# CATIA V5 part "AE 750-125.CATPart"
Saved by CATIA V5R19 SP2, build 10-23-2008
Part number: AE 750-125
Bounding box of the stored display mesh (mm): x -24.865 to 24.865, y -24.997 to 24.997, z 0 to 300
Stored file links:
  C:\Users\Bora\Desktop\3D Katı model\AE serisi\AE 750\AE 750-125.CATPart
  C:\Program Files\Dassault Systemes\B19\intel_a\reffiles\standard\MetricThickPitch.txt
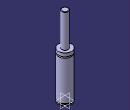
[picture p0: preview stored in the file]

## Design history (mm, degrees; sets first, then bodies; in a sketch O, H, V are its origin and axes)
Body1 (main body)
  Sketch1 on yz-plane, origin (0, 0, 0), H (0, 1, 0), V (0, 0, 1)
    point P1 (25, 157.5)
    point P8 (25, 161.5)
    point P9 (12.5, 298)
    point P11 (12.5, 298)
    point P13 (25, 161.5)
    point P14 (25, 157.5)
    line L1 (25, 157.5) -> (25, 8)
    line L2 (25, 4) -> (25, 0)
    line L3 (21.5, 8) -> (21.5, 4)
    line L4 (25, 174) -> (25, 161.5)
    line L5 (12.5, 298) -> (12.5, 174)
    arc A1 centre (10.5, 298) radius 2 from (12.5, 298) to (10.5, 300) ccw
    arc A2 centre (25, 159.5) radius 2 from (25, 161.5) to (25, 157.5) ccw
    line L6 (10.5, 300) -> (0, 300)
    point P15 (0, 300)
    line L7 (12.5, 174) -> (25, 174)
    line L8 (0, 0) -> (25, 0)
    line L9 (21.5, 8) -> (25, 8)
    line L10 (21.5, 4) -> (25, 4)
    coincidence: P15 V, P1 P14, P8 P13, P9 P11
    tangency: L6 A1
    horizontal: L7 H, L8 H, L9 H, L10 H
  Shaft1: profile Sketch1, axis Sketch1.V, angle 360
  Sketch2 on face of Shaft1 from Sketch1.L8, origin (0, 0, 0), H (1, 0, 0), V (0, -1, 0)
    point P1 (10, 0)
    distance P1 V = 10
  Hole1: placed by Sketch2, at (10, 0, 0) direction (0, 0, 1), diameter 6.647, depth 13, threaded "M8", thread diameter 8, thread depth 13, pitch 1.25
  CircPattern1: of Hole1, instances 2, angular step 180, axis from xy-plane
